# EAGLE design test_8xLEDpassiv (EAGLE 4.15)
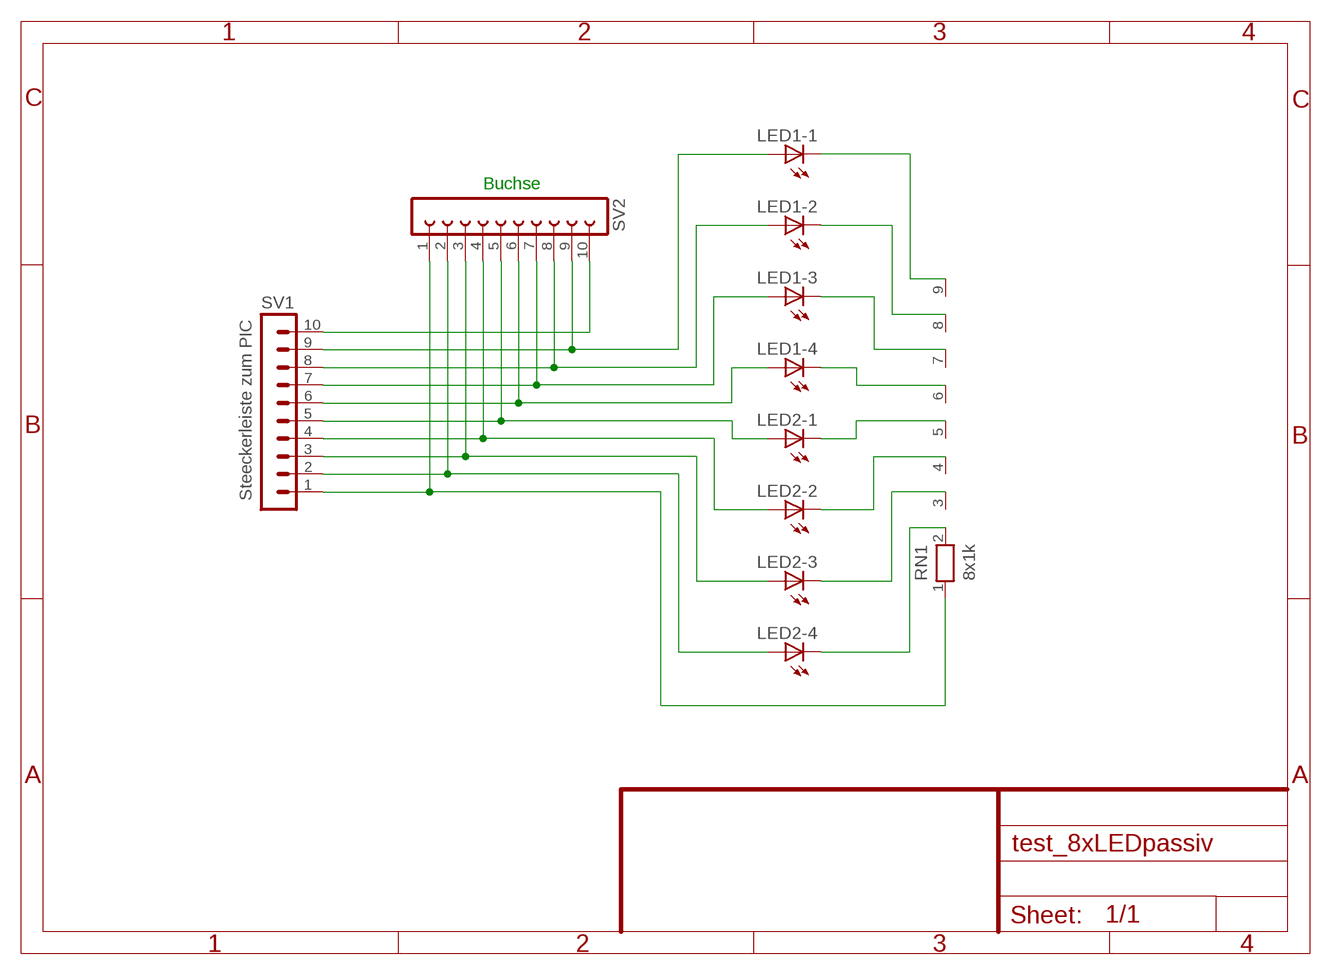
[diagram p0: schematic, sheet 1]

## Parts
LED1  LZR184  [LZR184]
LED2  LZR184  [LZR184]
RN1  8x1k  RN08  [RN-9]
SV1  Steeckerleiste zum PIC  MA10-1W  [MA10-1W]
SV2  FE10-1  [FE10]

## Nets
GND: RN1.1 SV1.1 SV2.1
N$1: LED1.A1(-1:A) SV1.9 SV2.9
N$2: LED1.A2(-2:A) SV1.8 SV2.8
N$3: LED1.A3(-3:A) SV1.7 SV2.7
N$5: LED2.A1(-1:A) SV1.5 SV2.5
N$6: LED2.A2(-2:A) SV1.4 SV2.4
N$7: LED2.A3(-3:A) SV1.3 SV2.3
N$8: LED2.A4(-4:A) SV1.2 SV2.2
N$12: LED1.A4(-4:A) SV1.6 SV2.6
N$19: LED2.K3(-3:C) RN1.3
N$20: LED2.K2(-2:C) RN1.4
N$21: LED2.K1(-1:C) RN1.5
N$22: LED1.K4(-4:C) RN1.6
N$23: LED1.K3(-3:C) RN1.7
N$24: LED1.K2(-2:C) RN1.8
N$25: LED1.K1(-1:C) RN1.9
N$27: LED2.K4(-4:C) RN1.2
VCC: SV1.10 SV2.10

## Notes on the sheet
- Buchse

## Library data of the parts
LED1 LED2 = led:LZR184: LED BLOCK 4 LEDs, Siemens
RN1 = resistor-net:RN08: RESISTOR NETWORK
SV1 = con-lstb:MA10-1W: PIN HEADER
SV2 = con-lsta:FE10-1: FEMALE HEADER

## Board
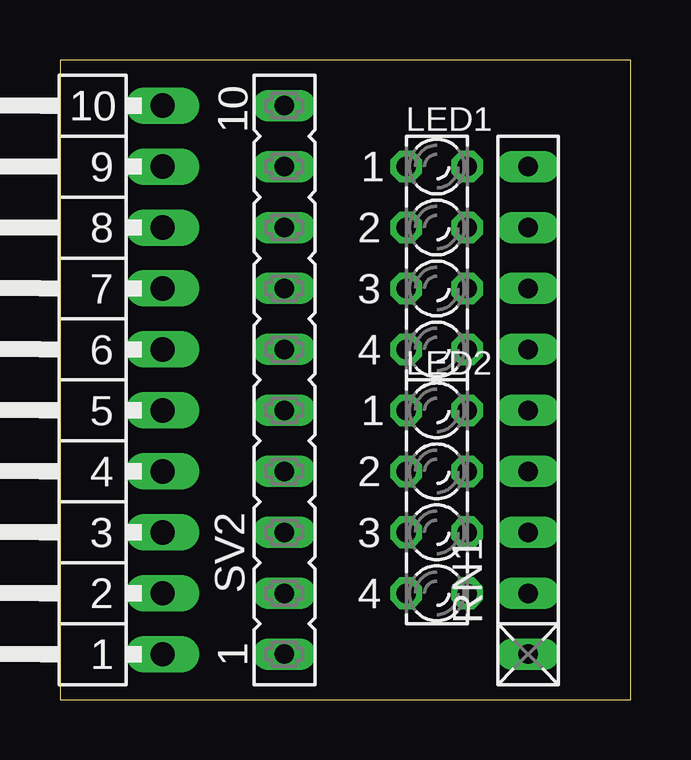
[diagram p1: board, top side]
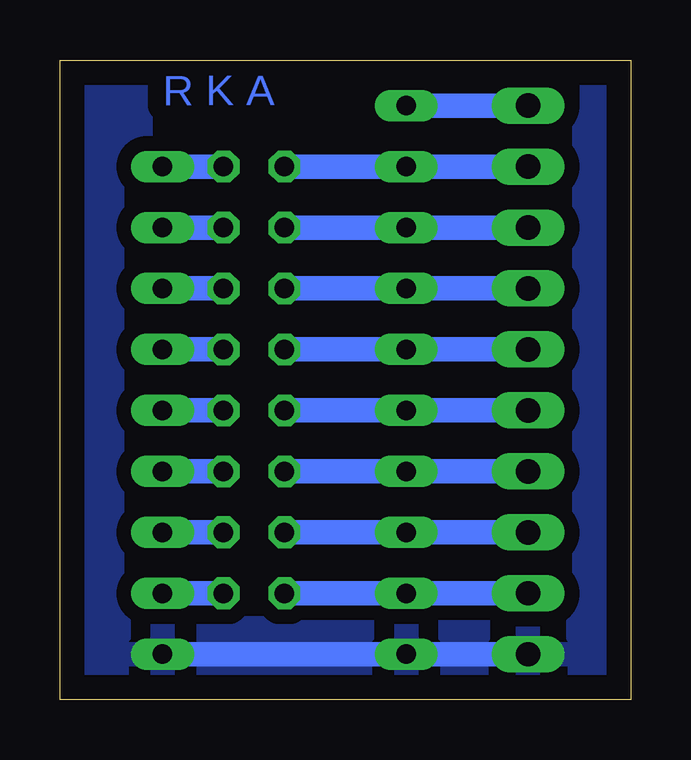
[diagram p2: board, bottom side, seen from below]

Size 23.8 x 26.66 mm. Coordinates in mm from the lower left corner, seen from the top.
Outline: 0,0 23.8,0 23.8,26.66 0,26.66 0,0
Copper layers (1*16): Top 0.035mm / dielectric 1.5mm / Bottom 0.035mm
Design rules "default": minimum track width 10mil, minimum drill 24mil, track to track 8mil, track to pad 8mil, pad to pad 8mil, via to via 8mil, smd to smd 8mil, copper to edge 40mil, drill to drill 8mil, minimum pad ring 10mil, minimum via ring 8mil, stop-mask expansion 4mil, vias tented up to drill 0mil, thermal gap 10mil

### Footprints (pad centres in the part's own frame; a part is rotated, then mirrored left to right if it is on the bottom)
LZR184 = drill 0.813 octagon: A1 -1.27,3.81; A2 -1.27,1.27; A3 -1.27,-1.27; A4 -1.27,-3.81; K1 1.27,3.81; K2 1.27,1.27; K3 1.27,-1.27; K4 1.27,-3.81
RN-9 = drill 0.813 long: 1 -10.16,0; 2 -7.62,0; 3 -5.08,0; 4 -2.54,0; 5 0,0; 6 2.54,0; 7 5.08,0; 8 7.62,0; 9 10.16,0
MA10-1W = drill 1.016 long: 1 -11.43,0; 2 -8.89,0; 3 -6.35,0; 4 -3.81,0; 5 -1.27,0; 6 1.27,0; 7 3.81,0; 8 6.35,0; 9 8.89,0; 10 11.43,0
FE10 = drill 0.813 long: 1 -11.43,0; 2 -8.89,0; 3 -6.35,0; 4 -3.81,0; 5 -1.27,0; 6 1.27,0; 7 3.81,0; 8 6.35,0; 9 8.89,0; 10 11.43,0

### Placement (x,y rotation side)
LED1  15.71,18.41 0 top
LED2  15.71,8.25 0 top
RN1  19.52,12.06 90 top
SV1  4.28,13.33 90 top
SV2  9.36,13.33 90 top

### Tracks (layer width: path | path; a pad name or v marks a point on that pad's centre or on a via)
GND
  Bottom 1.016: SV1.1 SV2.1 RN1.1
  pour Bottom (isolate 0.61): 0.47,27.3 24.6,27.3 24.6,-0.64 0.47,-0.64
N$1
  Bottom 1.016: SV1.9 SV2.9 LED1.A1
N$2
  Bottom 1.016: LED1.A2 SV2.8 SV1.8
N$3
  Bottom 1.016: SV1.7 SV2.7 LED1.A3
N$5
  Bottom 1.016: SV1.5 SV2.5 LED2.A1
N$6
  Bottom 1.016: LED2.A2 SV2.4 SV1.4
N$7
  Bottom 1.016: SV1.3 SV2.3 LED2.A3
N$8
  Bottom 1.016: LED2.A4 SV2.2 SV1.2
N$12
  Bottom 1.016: LED1.A4 SV2.6 SV1.6
N$19
  Bottom 1.016: LED2.K3 RN1.3
N$20
  Bottom 1.016: LED2.K2 RN1.4
N$21
  Bottom 1.016: LED2.K1 RN1.5
N$22
  Bottom 1.016: LED1.K4 RN1.6
N$23
  Bottom 1.016: LED1.K3 RN1.7
N$24
  Bottom 1.016: LED1.K2 RN1.8
N$25
  Bottom 1.016: LED1.K1 RN1.9
N$27
  Bottom 1.016: LED2.K4 RN1.2
VCC
  Bottom 1.016: SV1.10 SV2.10

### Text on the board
Bottom: R K A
